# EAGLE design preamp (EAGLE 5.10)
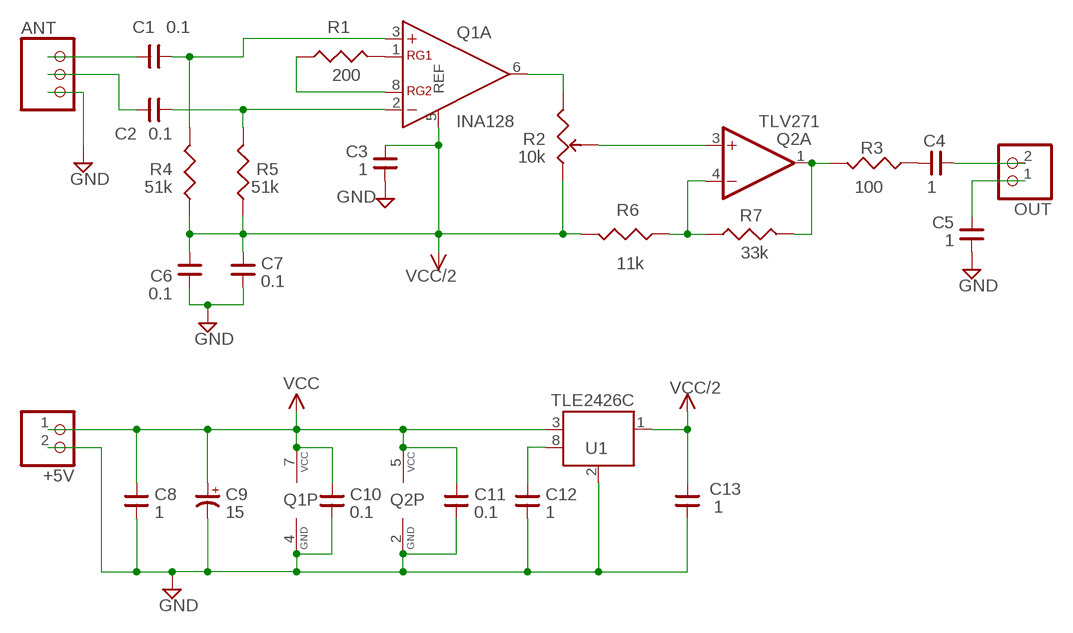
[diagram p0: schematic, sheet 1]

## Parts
+5V  HIROSE-1X2C  [HIROSE-1X2]
ANT  PINHD-1X3A  [1X03A]
C1  0.1  CAP-NPDC  [805C]
C2  0.1  CAP-NPDC  [805C]
C3  1  CAP-NPDC  [805C]
C4  1  CAP-NPDC  [805C]
C5  1  CAP-NPDC  [805C]
C6  0.1  CAP-NPDC  [805C]
C7  0.1  CAP-NPDC  [805C]
C8  1  CAP-NPDC  [805C]
C9  15  CAP-PH  [BC45196H-B]
C10  0.1  CAP-NPDC  [805C]
C11  0.1  CAP-NPDC  [805C]
C12  1  CAP-NPDC  [805C]
C13  1  CAP-NPDC  [805C]
OUT  PINHD-1X2A  [1X02A]
Q1  INA128  OPAMP-INSTRUMENTATIONA  [SO08]
Q2  TLV271  OPAMP-SINGLE  [SOT23-5]
R1  200  RESISTORC  [805C]
R2  10k  TRIMPOTA  [TRIMPOT-BOURNS-SMALL]
R3  100  RESISTORB  [805B]
R4  51k  RESISTORC  [805C]
R5  51k  RESISTORC  [805C]
R6  11k  RESISTORC  [805C]
R7  33k  RESISTORC  [805C]
U1  TLE2426C  TLE2426Y  [SO08]

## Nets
GND: +5V.2 ANT.3 C3.1 C5.1 C6.1 C7.1 C8.1 C9.- C10.1 C11.1 C12.1 C13.1 Q1.4(P:GND) Q2.2(P:GND) U1.2(COMMON)
N$1: ANT.1 C1.2
N$2: ANT.2 C2.2
N$3: Q1.1(A:RG1) R1.2
N$4: Q2.4(A:-IN) R6.1 R7.1
N$5: C5.2 OUT.1
N$6: Q1.8(A:RG2) R1.1
N$7: C2.1 Q1.2(A:-IN) R5.2
N$8: C4.2 R3.1
N$10: Q2.1(A:OUT) R3.2 R7.2
N$11: C1.1 Q1.3(A:+IN) R4.2
N$13: Q2.3(A:+IN) R2.2
N$15: C4.1 OUT.2
N$24: Q1.6(A:OUT) R2.1
N$25: C12.2 U1.8(NOISE)
VCC: +5V.1 C8.2 C9.+ C10.2 C11.2 Q1.7(P:VCC) Q2.5(P:VCC) U1.3(IN)
VCC/2: C3.2 C6.2 C7.2 C13.2 Q1.5(A:REF) R2.3 R4.1 R5.1 R6.2 U1.1(OUT)

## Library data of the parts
+5V = agarConn:HIROSE-1X2: Hirose DF3-2S-2C, 2 mm pin spacing.
ANT = agarConn:PINHD-1X3
C1-C8 C10-C13 = agar:CAP-NP: Non-polarized capacitor
C9 = agar:CAP-P: Polarized capacitor
OUT = agarConn:PINHD-1X2: PIN HEADER
Q1 = agar:OPAMP-INSTRUMENTATION: Instrumentation amplifier
Q2 = agar:OPAMP-SINGLE
R1 R3-R7 = agar:RESISTOR
R2 = agar:TRIMPOT
U1 = agar:TLE2426Y: Precision virtual ground

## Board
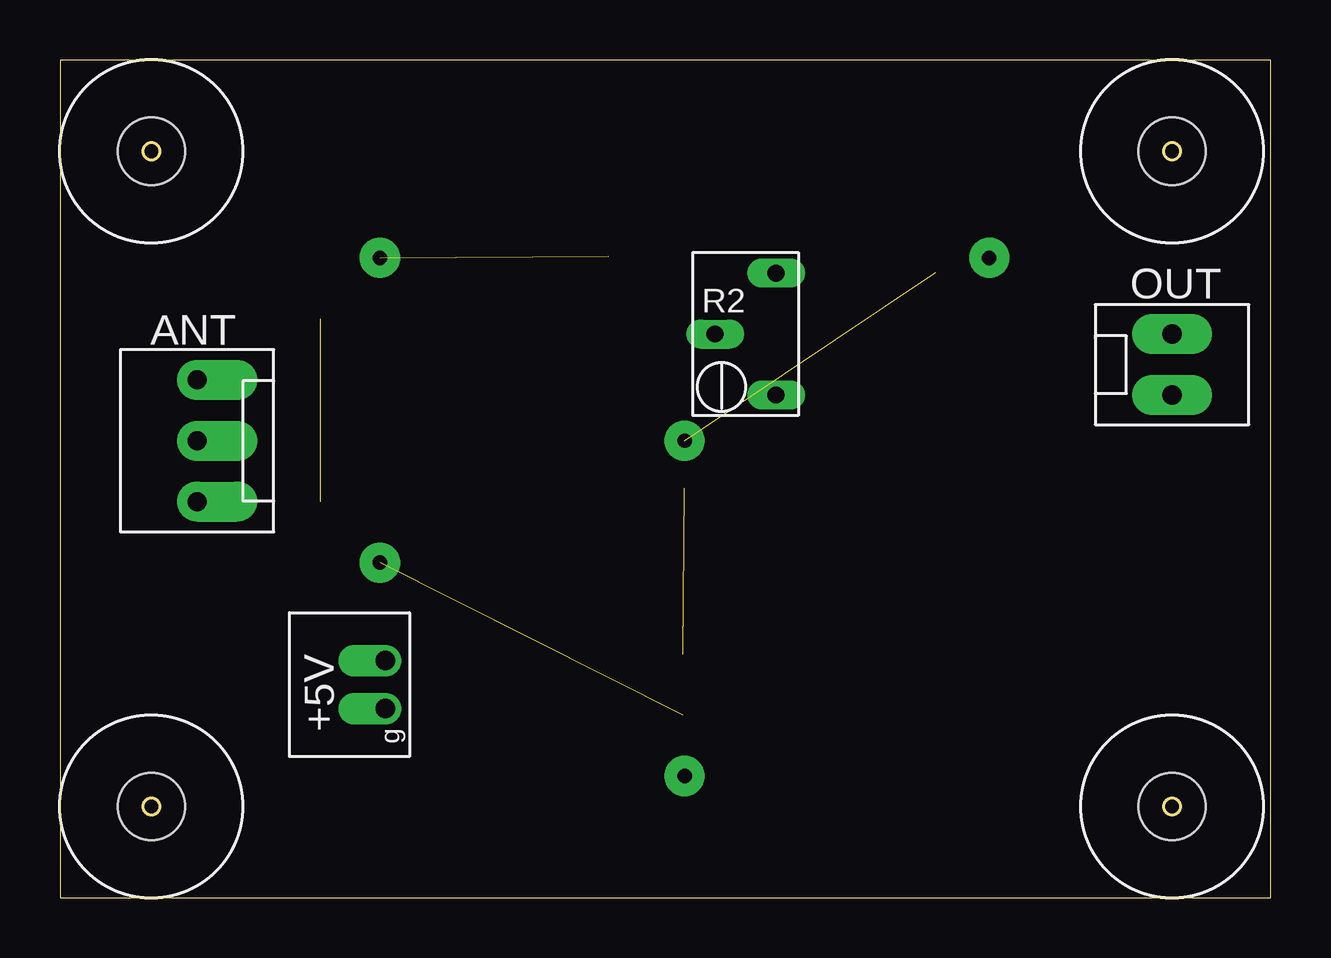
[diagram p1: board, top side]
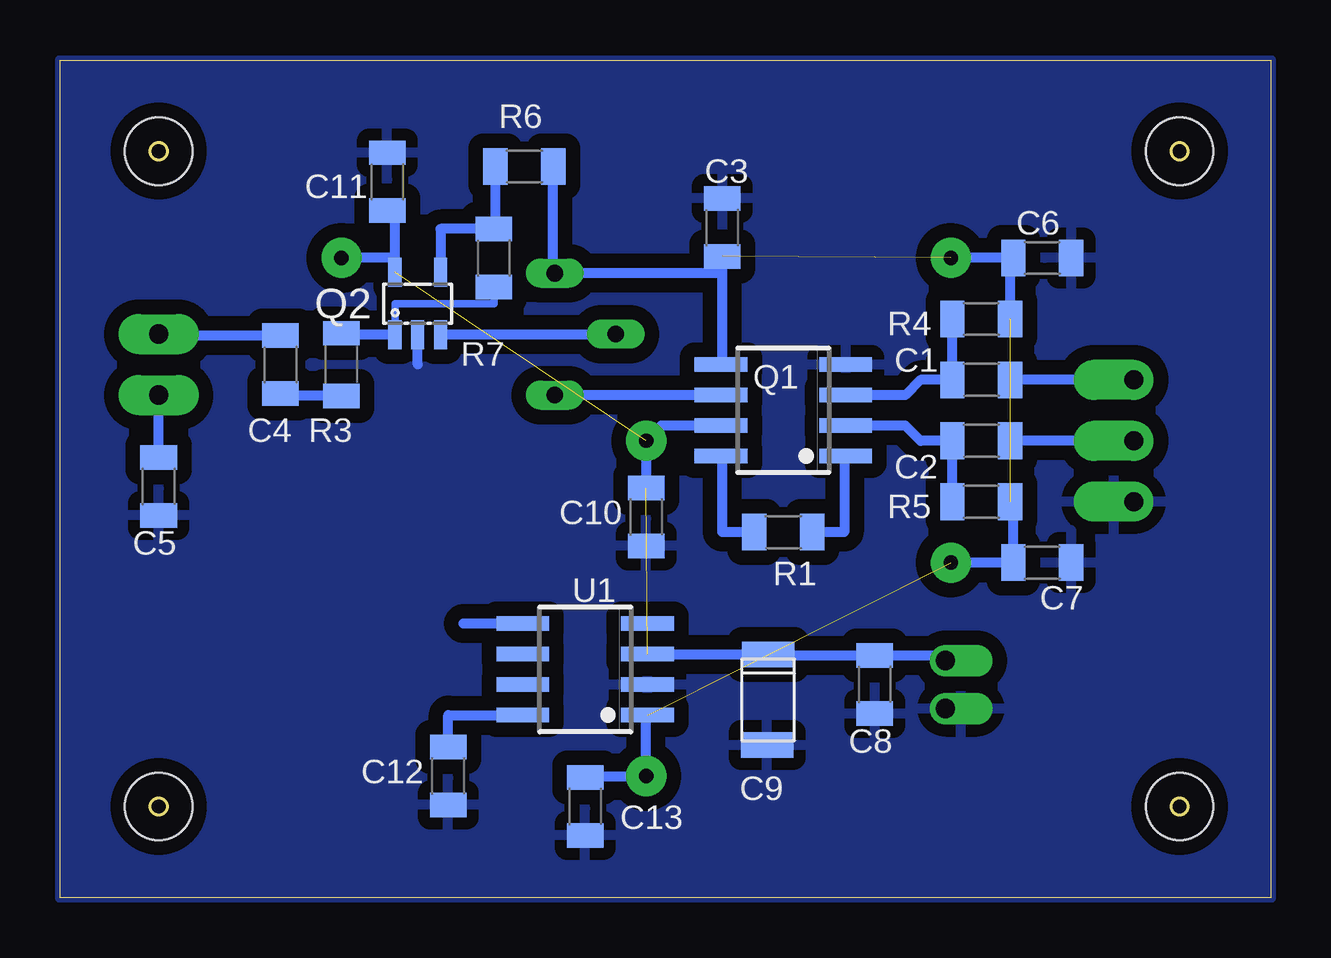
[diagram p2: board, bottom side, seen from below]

Size 50.47 x 34.91 mm. Coordinates in mm from the lower left corner, seen from the top.
Outline: 0,0 50.47,0 50.47,34.91 0,34.91 0,0
Copper layers (1*16): Top 0.035mm / dielectric 1.5mm / Bottom 0.035mm
Design rules "default *": minimum track width 10mil, minimum drill 24mil, track to track 8mil, track to pad 8mil, pad to pad 8mil, via to via 8mil, smd to smd 8mil, copper to edge 0mil, drill to drill 8mil, minimum pad ring 10mil, minimum via ring 8mil, stop-mask expansion 4mil, vias tented up to drill 0mil, thermal gap 20mil

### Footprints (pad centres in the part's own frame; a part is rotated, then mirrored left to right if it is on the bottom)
HIROSE-1X2 = drill 0.8 offset: 1 -1,1.5; 2 1,1.5
1X03A = drill 0.8 pad 1.676 offset: 1 0,2.54; 2 0,0; 3 0,-2.54
805C = smd 1.016 x 1.524: 1 -1.206,0; 2 1.206,0
BC45196H-B = smd 1.067 x 2.184: + -1.883,0; - 1.883,-0.038
1X02A = drill 0.8 pad 1.676 long: 1 0,1.27; 2 0,-1.27
SO08 = smd 0.6 x 2.2: 1 -1.905,-2.6; 2 -0.635,-2.6; 3 0.635,-2.6; 4 1.905,-2.6; 5 1.905,2.6; 6 0.635,2.6; 7 -0.635,2.6; 8 -1.905,2.6
SOT23-5 = smd 0.55 x 1.2: 1 -0.95,-1.3; 2 0,-1.3; 3 0.95,-1.3; 4 0.95,1.3; 5 -0.95,1.3
TRIMPOT-BOURNS-SMALL = drill 0.7 pad 1.016 long: 1 2.54,1.27; 2 0,-1.27; 3 -2.54,1.27
805B = smd 1.016 x 1.524: 1 -1.306,0; 2 1.306,0
MOUNTING-HOLE-PLAIN = hole 2.8: 0,0

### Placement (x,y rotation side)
+5V  12.06,8.89 270 top
ANT  5.71,19.05 0 top
C1  12.06,21.59 0 bottom
C2  12.06,19.05 0 bottom
C3  22.86,27.94 270 bottom
C4  41.27,22.23 270 bottom
C5  46.35,17.14 90 bottom
C6  9.53,26.67 180 bottom
C7  9.53,13.97 180 bottom
C8  16.51,8.89 90 bottom
C9  20.95,8.26 270 bottom
C10  26.04,15.88 90 bottom
C11  36.83,29.84 270 bottom
C12  34.29,5.08 90 bottom
C13  28.57,3.81 90 bottom
OUT  46.35,22.23 180 top
Q1  20.32,20.32 90 bottom
Q2  35.56,24.77 0 bottom
R1  20.32,15.24 0 bottom
R2  28.57,23.5 270 top
R3  38.73,22.23 90 bottom
R4  12.06,24.13 180 bottom
R5  12.06,16.51 180 bottom
R6  31.11,30.48 0 bottom
R7  32.38,26.67 270 bottom
U1  28.57,9.53 90 bottom
U$3  [MOUNTING-HOLE-PLAIN]  3.81,3.81 0 top
U$4  [MOUNTING-HOLE-PLAIN]  46.35,3.81 0 top
U$5  [MOUNTING-HOLE-PLAIN]  3.81,31.11 0 top
U$6  [MOUNTING-HOLE-PLAIN]  46.35,31.11 0 top

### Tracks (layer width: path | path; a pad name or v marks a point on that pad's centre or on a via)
GND
  Bottom 0.406: 35.56,22.23 Q2.2
  pour Bottom (isolate 0.61): 0,0 50.47,0 50.47,34.91 0,34.91
N$1
  Bottom 0.406: ANT.1 C1.2
N$2
  Bottom 0.406: ANT.2 C2.2
N$3
  Bottom 0.406: Q1.1 17.78,18.41 17.78,15.24 R1.2
N$4
  Bottom 0.406: Q2.4 34.61,27.88 R7.1 32.32,27.88 R6.1
N$5
  Bottom 0.406: C5.2 OUT.1
N$6
  Bottom 0.406: Q1.8 22.86,18.41 22.86,15.24 R1.1
N$7
  Bottom 0.406: Q1.2 15.24,19.68 14.61,19.05 C2.1 R5.2
N$8
  Bottom 0.406: R3.1 41.27,20.92 C4.2
N$9
  Bottom 0.406: 31.11,11.43 33.66,11.43
N$10
  Bottom 0.305: R7.2 32.38,24.77 36.51,24.77 Q2.1
  Bottom 0.406: Q2.1 38.73,23.46 R3.2
N$11
  Bottom 0.406: Q1.3 15.24,20.95 14.61,21.59 C1.1 R4.2
N$13
  Bottom 0.406: Q2.3 27.3,23.46 R2.2
N$15
  Bottom 0.406: C4.1 46.35,23.43 OUT.2
N$24
  Bottom 0.406: Q1.6 R2.1
N$25
  Bottom 0.406: U1.8 34.29,7.62 C12.2
VCC  (via drill 0.6 pad 1.68)  (2 unrouted)
  Bottom 0.406: C11.2 36.51,28.64 36.51,26.67 | Q2.5 36.51,26.67 | Q1.7 25.4,19.68 v26.04,19.05 C10.2 | 36.51,26.67 v38.73,26.67 | +5V.1 13.56,10.1 C8.2 20.95,10.1 C9.+ 25.98,10.14 U1.3
VCC/2  (via drill 0.6 pad 1.68)  (3 unrouted)
  Bottom 0.406: R5.1 10.73,16.38 C7.2 v13.34,13.97 | Q1.5 22.86,22.23 22.86,26.04 | 22.86,26.04 C3.2 | R6.2 29.91,26.04 R2.3 22.86,26.04 | U1.1 26.04,7.62 v26.04,5.08 28.57,5.08 C13.2 | v13.34,26.67 C6.2 10.86,26.67 R4.1

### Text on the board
Document: vcc/2 | vcc/2 | vcc | vcc | vcc/2 | vcc/2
